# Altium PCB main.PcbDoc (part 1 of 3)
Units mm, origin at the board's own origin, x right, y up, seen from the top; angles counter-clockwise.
Board outline 326.29 x 232.51 mm, 2 copper layers (TopLayer, BottomLayer); 87 components, 134 nets, 466 pads, 108 vias.
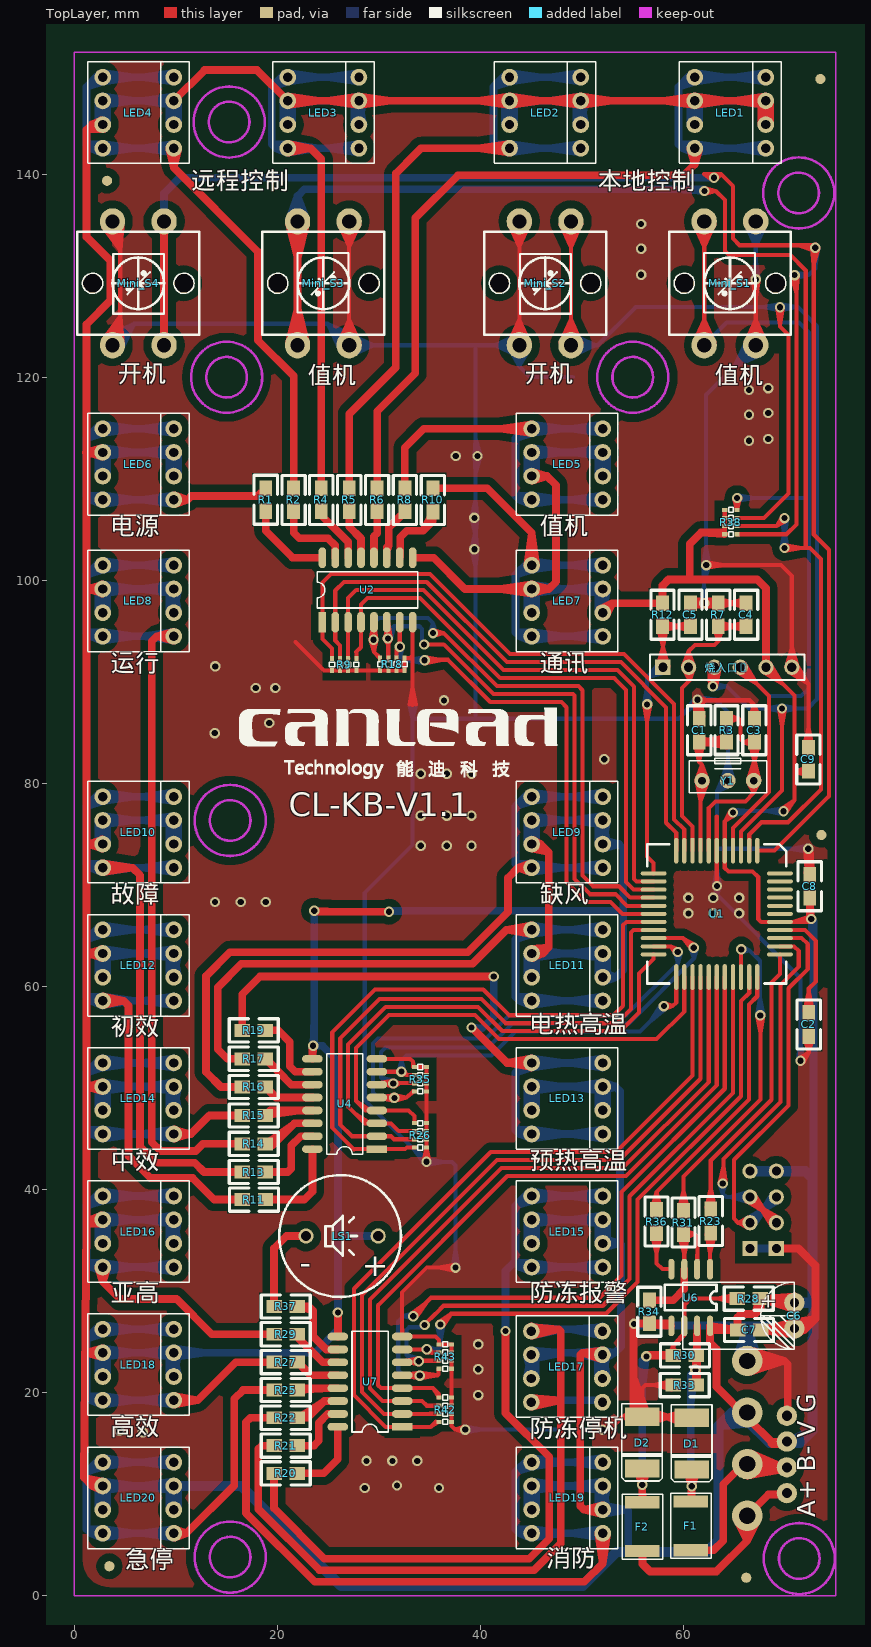
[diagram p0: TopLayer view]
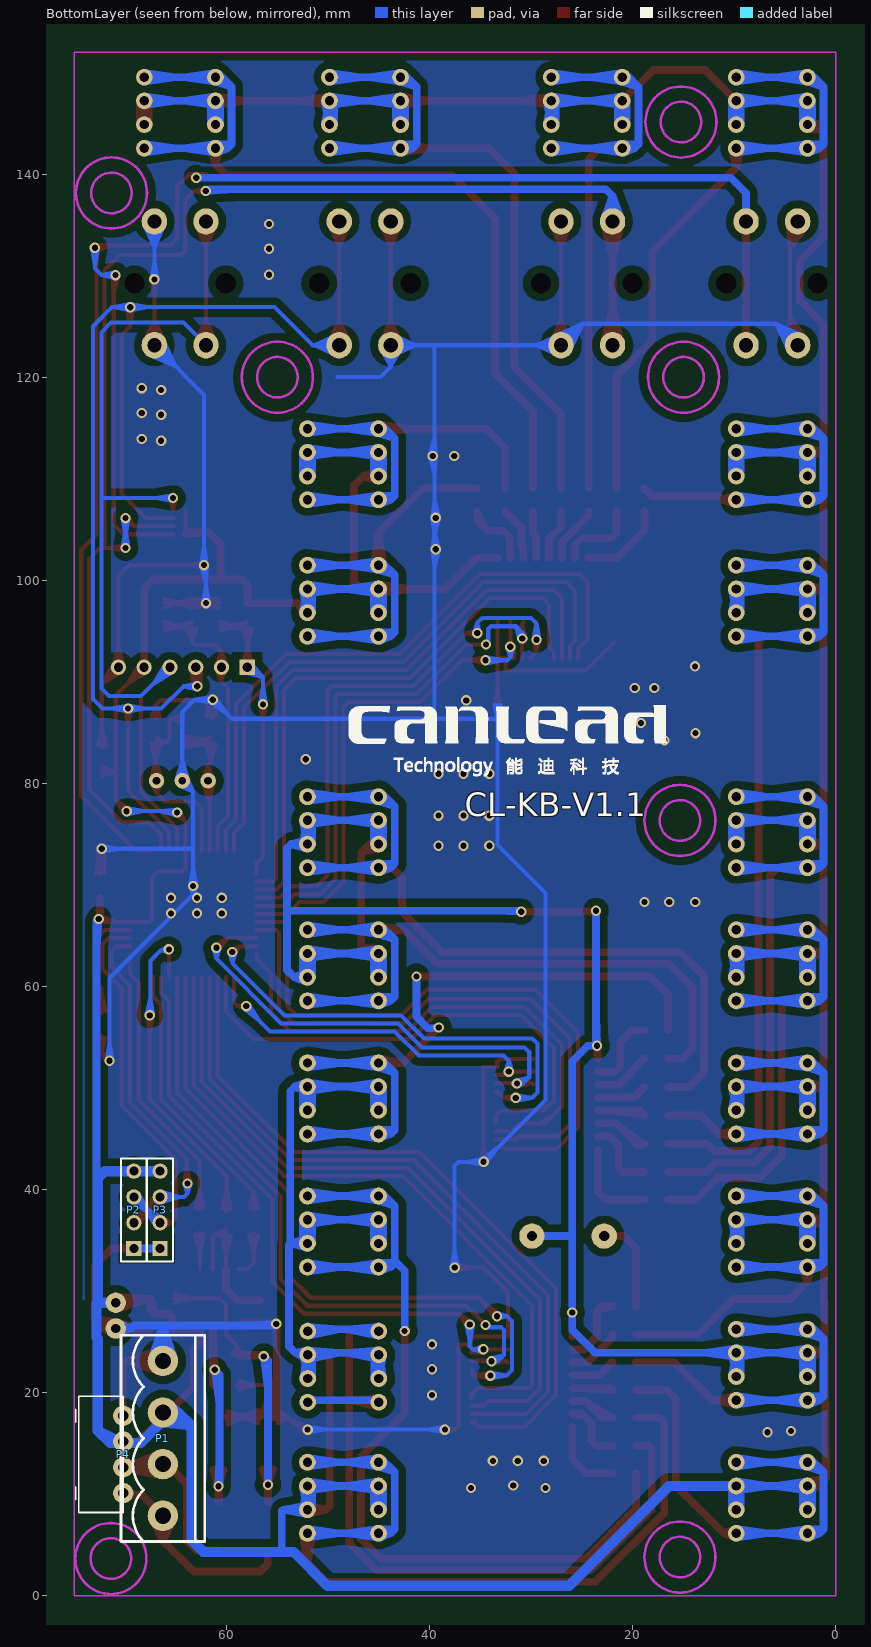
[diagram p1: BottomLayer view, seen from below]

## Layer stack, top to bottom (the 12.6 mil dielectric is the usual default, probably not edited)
TopLayer: signal copper 0.0356
Dielectric: dielectric 0.32, FR-4, Dk 4.8
BottomLayer: signal copper 0.0356

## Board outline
264.52,193.895 -60.795,193.895 -60.795,-38.612 265.497,-38.612 265.497,183.149

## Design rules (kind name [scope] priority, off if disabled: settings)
Clearance Clearance_1 [All] p1 off: gap=0.762
Clearance [All] p2: gap=0.381
ComponentClearance [All] p1 off: gap=0.254 collisioncheckmode=3 verticalgap=0.254 showdistances=FALSE
FabricationTestPointUsage TestPointUsage [All] p1: valid=0 allowmultiple=FALSE
FabricationTestpoint Testpoint [(IsPad And (OnTopLayer Or OnBottomLayer))] p1: side=3 testpointundercomponent=TRUE minsize=1.016 maxsize=2.54 preferedsize=1.524 minholesize=0.508 maxholesize=1.016 preferedholesize=0.813 testpointgrid=0.025 allowsidetop=TRUE allowsidebottom=TRUE usegrid=TRUE gridtolerance=0
PolygonConnect PolygonConnect_1 [All vs (InPadClass('All Pads'))] p1: connectstyle=NoConnect reliefconductorwidth=0.254 reliefentries=4 polygonreliefangle="90 Angle"
PolygonConnect [All] p2: connectstyle=Direct reliefconductorwidth=0.254 reliefentries=4 polygonreliefangle="90 Angle"
RoutingVias [All] p1: holewidth=0.61 width=1.016 viastyle="Through Hole" minholewidth=0.61 minwidth=1.016 maxholewidth=0.61 maxwidth=1.016
SilkscreenOverComponentPads [All] p1: minsilkscreentomaskgap=0.254
SolderMaskExpansion [All] p1: expansion=0.102
Width [All] p1: maxlimit=7.62 minlimit=0.254 preferedwidth=0.762
24 further rules are at their usual default settings.

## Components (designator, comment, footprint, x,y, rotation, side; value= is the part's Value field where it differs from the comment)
C1 "22p" 0805 61.551,84.093 r90 top
C2 "104" 0805 72.339,55.118 r90 top
C3 "22p" 0805 66.987,84.093 r90 top
C4 "104" 0805 66.174,95.472 r90 top
C5 "104" 0805 60.687,95.472 r90 top
C6 "470u/16V" E6.5MM*10 70.917,27.584 r270 top
C7 "104" 0805 65.329,26.162 r0 top
C8 "104" 0805 72.441,68.732 r90 top
C9 "104" 0805 72.3,81.225 r90 top
D1 "SMBJ6.8" SMBJ_SMT 60.808,14.986 r270 top
D2 "SMBJ6.8" SMBJ_SMT 55.93,15.081 r270 top
F1 "X14" PPTC_SMT 60.73,6.881 r90 top
F2 "X14" PPTC_SMT 55.955,6.806 r90 top
LED1 "GREEN" PLED10*10 64.599,146.05 r0 top
LED2 "GREEN" PLED10*10 46.369,146.05 r0 top
LED3 "GREEN" PLED10*10 24.529,146.05 r0 top
LED4 "GREEN" PLED10*10 6.299,146.05 r0 top
LED5 "GREEN" PLED10*10 48.539,111.43 r0 top
LED6 "GREEN" PLED10*10 6.299,111.43 r0 top
LED7 "GREEN" PLED10*10 48.539,97.98 r0 top
LED8 "GREEN" PLED10*10 6.299,97.98 r0 top
LED9 "RED" PLED10*10 48.539,75.19 r0 top
LED10 "RED" PLED10*10 6.299,75.19 r0 top
LED11 "RED" PLED10*10 48.539,62.08 r0 top
LED12 "RED" PLED10*10 6.299,62.08 r0 top
LED13 "RED" PLED10*10 48.539,48.97 r0 top
LED14 "RED" PLED10*10 6.299,48.97 r0 top
LED15 "RED" PLED10*10 48.539,35.86 r0 top
LED16 "RED" PLED10*10 6.299,35.86 r0 top
LED17 "RED" PLED10*10 48.514,22.555 r0 top
LED18 "RED" PLED10*10 6.299,22.75 r0 top
LED19 "RED" PLED10*10 48.539,9.64 r0 top
LED20 "RED" PLED10*10 6.299,9.64 r0 top
LS1 "Speaker" SPK 29.921,35.408 r180 top
Mini_S1 "" KEYL 64.574,129.25 r270 top
Mini_S2 "" KEYL 46.369,129.25 r90 top
Mini_S3 "" KEYL 24.529,129.25 r270 top
Mini_S4 "" KEYL 6.299,129.25 r90 top
P1 "Header 4" PL4X 66.275,15.5 r270 bottom
P2 "Header 4" HDR1X4 69.139,34.188 r90 bottom
P3 "Header 4" HDR1X4 66.548,34.188 r90 bottom
P4 "Header 4" C3-4L 70.175,13.91 r270 bottom
R1 "220" 0805 18.849,109.072 r270 top
R2 "220" 0805 21.592,109.067 r270 top
R3 "1M" 0805 64.243,84.093 r90 top
R4 "220" 0805 24.317,109.067 r270 top
R5 "220" 0805 27.067,109.067 r270 top
R6 "220" 0805 29.817,109.067 r270 top
R7 "3K" 0805 63.431,95.472 r90 top
R8 "220" 0805 32.542,109.067 r270 top
R9 "Res Pack42" RES4 25.374,91.1 r0 top
R10 "220" 0805 35.299,109.05 r270 top
R11 "220" 0805 16.549,39 r0 top
R12 "3K" 0805 57.944,95.472 r90 top
R13 "220" 0805 16.533,41.717 r0 top
R14 "220" 0805 16.533,44.492 r0 top
R15 "220" 0805 16.533,47.292 r0 top
R16 "220" 0805 16.533,50.092 r0 top
R17 "220" 0805 16.533,52.867 r0 top
R18 "Res Pack4" RES4 30.124,91.125 r0 top
R19 "220" 0805 16.533,55.667 r0 top
R20 "220" 0805 19.683,12.042 r0 top
R21 "220" 0805 19.683,14.767 r0 top
R22 "220" 0805 19.683,17.517 r0 top
R23 "100" 0805 62.687,35.763 r90 top
R25 "220" 0805 19.683,20.242 r0 top
R26 "Res Pack4" RES4 34.692,44.142 r90 top
R27 "220" 0805 19.683,22.992 r0 top
R28 "3K" 0805 67.564,29.261 r180 top
R29 "220" 0805 19.683,25.742 r0 top
R30 "10K?" 0805 61.265,23.673 r180 top
R31 "100" 0805 59.995,35.611 r90 top
R33 "3K" 0805 58.979,20.726 r0 top
R34 "30K" 0805 56.642,26.822 r90 top
R35 "Res Pack4" RES4 34.692,49.667 r90 top
R36 "100" 0805 57.353,35.712 r90 top
R37 "220" 0805 21.958,28.492 r180 top
R38 "Res Pack42" RES4 64.059,106.934 r270 top
R42 "Res Pack4" RES4 37.135,17.12 r90 top
R43 "Res Pack4" RES4 37.135,22.352 r90 top
U1 "QFP44" QFP44 63.274,67.15 r270 top
U2 "2003" SO_16 28.874,99.05 r0 top
U4 "2003" SO_16 26.624,48.425 r90 top
U6 "U485" SOP8 60.706,29.362 r180 top
U7 "2003" SO_16 29.124,21.075 r90 top
Y1 "10M" X3 64.364,80.264 r0 top
烧入口1 "Rin1" HDR1X6 57.963,91.44 r0 top

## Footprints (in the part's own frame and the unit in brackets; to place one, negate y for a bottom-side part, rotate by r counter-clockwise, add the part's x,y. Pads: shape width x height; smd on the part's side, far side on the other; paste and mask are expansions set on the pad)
0805 [mil]
  rect 60x50 smd: 1(-0.2,0.31) 2(89.8,0.31)
  silkscreen extent -50,-45 140,45
C3-4L [mm]
  round 2 hole 1: 1(-3.81,0) 2(-1.27,0) 3(1.27,0) 4(3.81,0)
  silkscreen extent -5.72,-4.7 5.71,0
E6.5MM*10 [mm]
  round 2 hole 0.9: 1(-1.27,0) 2(1.27,0)
  silkscreen extent -3.3,-11 3.3,0
HDR1X4 [mm] "Connector; Header; 4 Position"
  rect 1.5x1.5 hole 0.9: 1(0,0)
  round 1.5 hole 0.9: 2(2.54,0) 3(5.08,0) 4(7.62,0)
  silkscreen extent -1.27,-1.27 8.89,1.27
HDR1X6 [mm] "Connector;"
  rect 1.5x1.5 hole 0.9: 1(0,0)
  round 1.5 hole 0.9: 2(2.54,0) 3(5.08,0) 4(7.62,0) 5(10.16,0) 6(12.7,0)
  silkscreen extent -1.27,-1.27 13.97,1.27
KEYL [mil]
  round 65 hole 78.74 unplated: 0(0,177.17) 0(0,-177.17)
  oval 102x98 hole 55: 1(-240,-100) 1(240,-100) 2(-240,100) 2(240,100)
  silkscreen extent -200,-236 200,236
PL4X [mm]
  round 3 hole 1.6: 1(-7.62,0) 2(-2.54,0) 3(2.54,0) 4(7.62,0)
  silkscreen extent -10.16,-4.13 10.16,4.13
PLED10*10 [mil]
  round 65 hole 36: A(-137.8,-45.93) A(-137.8,45.93) A(137.8,-45.93) A(137.8,45.93) K(-137.8,-137.8) K(-137.8,137.8) K(137.8,-137.8) K(137.8,137.8)
  silkscreen extent -197,-197 197,197
PPTC_SMT [mm]
  rect 1.2x3.4 smd: 1(-2.4,0) 2(2.4,0)
  silkscreen extent -3.2,-2 3.2,2
QFP44 [mil]
  oval 100x16 smd: 1(-245,157) 2(-245,126) 3(-245,94) 4(-245,63) 5(-245,31) 6(-245,0) 7(-245,-31) 8(-245,-63) 9(-245,-94) 10(-245,-126) 11(-245,-157) 23(245,-157) 24(245,-126) 25(245,-94) 26(245,-63) 27(245,-31) 28(245,0) 29(245,31) 30(245,63) 31(245,94) 32(245,126) 33(245,157)
  oval 16x100 smd: 12(-157,-245) 13(-126,-245) 14(-94,-245) 15(-63,-245) 16(-31,-245) 17(0,-245) 18(31,-245) 19(63,-245) 20(94,-245) 21(126,-245) 22(157,-245) 34(157,245) 35(126,245) 36(94,245) 37(63,245) 38(31,245) 39(0,245) 40(-31,245) 41(-63,245) 42(-94,245) 43(-126,245) 44(-157,245)
  silkscreen extent -270,-270 270,270
RES4 [mm]
  rect 0.4x0.5 smd: 1(0,0) 2(0.8,0) 3(1.6,0) 4(2.4,0) 5(2.4,1.2) 6(1.6,1.2) 7(0.8,1.2) 8(0,1.2)
  silkscreen extent -0.25,0.38 2.65,0.85
SMBJ_SMT [mm]
  rect 1.778x3.4 smd: A(-2.54,0) K(2.54,0)
  silkscreen extent -3.81,-2 3.78,2
SO_16 [mil]
  rect 30x80 smd: 1(-175,-125)
  oval 30x80 smd: 2(-125,-125) 3(-75,-125) 4(-25,-125) 5(25,-125) 6(75,-125) 7(125,-125) 8(175,-125) 9(175,125) 10(125,125) 11(75,125) 12(25,125) 13(-25,125) 14(-75,125) 15(-125,125) 16(-175,125)
  silkscreen extent -195,-70 195,70
SOP8 [mil]
  oval 24x80 smd: 1(-75,-110) 2(-25,-110) 3(25,-110) 4(75,-110) 5(75,110) 6(25,110) 7(-25,110) 8(-75,110)
  silkscreen extent -100,-50 100,50
SPK [mm]
  round 1.5 / inner round 1.5 / far side round 2.5 hole 1: 1(-0.007,-0.008) 2(7.105,-0.008)
  silkscreen extent -2.26,-6.01 9.74,5.99
X3 [mil]
  round 60 hole 30: 1(-100,0) 2(100,0) 3(0,0)
  silkscreen extent -150,-47 150,107

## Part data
C1 C2 C3 C4 C5 C6 C7 C8 C9: library part CAP, "Capacitor"
D1 D2: library part DIODE, "Diode"
F1 F2: library part "Fuse 1", "Fuse"
LED1 LED2 LED3 LED4 LED5 LED6 LED7 LED8 LED9 LED10 LED11 LED12 LED13 LED14 LED15 LED16 LED17 LED18 LED19 LED20: library part LED, "Zener Diode"
LS1: "Loudspeaker"
Mini_S1 Mini_S2 Mini_S3 Mini_S4: library part SW-PB, "Switch"
P1 P2 P3 P4: "Header, 4-Pin"
R1 R2 R3 R4 R5 R6 R7 R8 R10 R11 R12 R13 R14 R15 R16 R17 R19 R20 R21 R22 R23 R25 R27 R28 R29 R30 R31 R33 R34 R36 R37: library part RES2
R9 R38: library part "Res Pack4", "Isolated Resistor Network"
R18 R26 R35 R42 R43: "Isolated Resistor Network"
U1: library part S3F84UA
U2 U4 U7: library part ULN2003A, "High-Voltage, High-Current Darlington Array"
Y1: library part CRYSTAL2
烧入口1: library part "Header 6", "Header, 6-Pin"

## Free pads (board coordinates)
  round 1 smd: 1(3.224,139.346) 1(3.45,2.9) 1(66.174,1.771) 1(73.474,149.371) 1(73.574,74.921)
  round 2.2 on Top Solder: 2(3.224,139.346) 2(3.45,2.9) 2(31.274,5.571) 2(66.174,1.771) 2(73.474,149.371) 2(73.574,74.921)

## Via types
v1: diameter 1.016, hole 0.61, TopLayer to BottomLayer, tented both sides, 108 vias

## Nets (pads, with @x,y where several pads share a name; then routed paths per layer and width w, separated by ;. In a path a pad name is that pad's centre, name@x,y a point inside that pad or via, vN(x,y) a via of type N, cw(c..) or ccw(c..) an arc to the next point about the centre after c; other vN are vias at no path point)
AD1: U1.42
AD2: U1.41
AD3: U1.40
AD4: U1.39
DE/RE: U1.43
DE/RE2: R31.2 U1.31 | length 52.8
  TopLayer w0.406: R31.2@59.558,38.069 59.987,39.873 ; R31.2@59.987,37.892 59.987,41.288 67.564,48.865 v1(67.564,57.15) 67.564,55.423 ; R31.2@59.987,38.019 59.987,39.873 ; R31.2@60.416,38.069 59.987,39.873 ; U1.31@65.662,60.927 65.662,63.63 v1(65.684,63.652) ; U1.31@65.662,61.994 v1@65.662,63.416 ; v1@67.26,57.123 67.564,55.423 ; v1@67.868,57.123 67.564,55.423
  BottomLayer w0.406: v1@65.704,63.348 66.497,63.551 ; v1@65.778,63.943 66.497,63.551 ; v1@67.26,57.168 67.513,58.88 ; v1@67.867,57.186 67.513,58.88 ; 66.497,63.551 65.583,63.551 v1(65.684,63.652) 66.497,63.551 ; 66.497,63.551 67.513,62.535 67.513,57.201 v1(67.564,57.15) 67.513,58.88
DL_CLK: 
DL_SDA: 
GND: C1.2 C2.1 C3.2 C4.2 C5.2 C6.2 C7.2 C8.2 C9.2 D1.A D2.A Mini_S1.2 Mini_S2.2 Mini_S3.2 Mini_S4.2 P1.1 P2.1 P3.1 P4.1 R7.2 R9.1 R9.2 R9.3 R9.4 R18.1 R18.2 R18.3 R18.4 R18.5 R26.1 R26.2 R26.3 R26.4 R33.1 R34.1 R35.1 R35.2 R35.3 R35.4 R35.5 R42.1 R42.2 R42.3 R42.4 R43.1 R43.2 R43.3 R43.4 R43.5 U1.6 U2.8 U4.8 U6.5 U7.8 Y1.3 烧入口1.6 | length 1190.7
  TopLayer w0.406: Mini_S4.2@2.821,123.656 4.526,126.002 ; Mini_S4.2@2.821,134.844 4.526,132.498 ; Mini_S4.2@3.169,123.439 4.526,126.002 ; Mini_S4.2@3.169,135.061 4.526,132.498 ; Mini_S4.2@3.541,123.274 4.526,126.002 ; Mini_S4.2@3.541,135.226 4.526,132.498 ; Mini_S4.2@3.759,123.154 4.526,123.921 4.526,134.579 Mini_S4.2@3.759,135.346 ; Mini_S4.2@3.759,123.205 4.526,126.002 ; Mini_S4.2@3.759,135.295 4.526,132.498 ; Mini_S4.2@3.982,123.153 4.526,126.002 ; Mini_S4.2@3.982,135.347 4.526,132.498 ; Mini_S4.2@4.386,123.105 4.526,126.002 ; Mini_S4.2@4.386,135.395 4.526,132.498 ; Mini_S4.2@4.797,123.114 4.526,126.002 ; Mini_S4.2@4.797,135.386 4.526,132.498 ; 21.793,93.929 24.597,91.125 ; 24.754,91.125 R9.2@26.174,91.1 ; R9.1@25.543,91.103 R9.3@26.974,91.1 ; R9.1@25.554,91.125 R9.3@26.974,91.1 ; Mini_S3.2@26.051,123.425 27.069,125.669 ; Mini_S3.2@26.051,135.075 27.069,132.831 ; R9.2@26.343,91.103 R9.4@27.774,91.1 ; R9.2@26.354,91.125 R9.4@27.774,91.1 ; Mini_S3.2@26.439,123.287 27.069,125.669 ; Mini_S3.2@26.439,135.213 27.069,132.831 ; Mini_S3.2@26.841,123.215 27.069,125.669 ; Mini_S3.2@26.841,135.285 27.069,132.831 ; Mini_S3.2@27.069,123.154 Mini_S3.2@27.069,135.346 ; Mini_S3.2@27.069,123.205 27.069,125.669 ; Mini_S3.2@27.069,135.295 27.069,132.831 ; Mini_S3.2@27.298,123.215 27.069,125.669 ; Mini_S3.2@27.298,135.285 27.069,132.831 ; Mini_S3.2@27.699,123.287 27.069,125.669 ; Mini_S3.2@27.699,135.213 27.069,132.831 ; Mini_S3.2@28.087,123.425 27.069,125.669 ; Mini_S3.2@28.087,135.075 27.069,132.831 ; 28.705,91.125 R18.1@30.124,91.125 ; 29.195,91.125 R9.4@27.774,91.1 ; U4.8@29.799,52.87 33.079,52.87 33.349,52.6 ; U4.8@30.434,52.87 32.034,52.87 ; 32.282,27.121 U7.8@32.299,25.52 ; U7.8@32.934,25.52 34.534,25.52 ; 33.021,87.758 33.319,89.459 ; 33.319,93.64 U2.8@33.319,95.24 ; U2.8@33.319,95.875 33.319,92.595 ; R35.5@33.349,52.075 33.349,52.6 ; R35.5@33.442,52.067 33.349,52.6 ; 33.628,87.759 33.319,89.459 ; 34.692,48.247 R35.1@34.692,49.667 ; 37.135,20.933 R43.1@37.135,22.352 ; v1@37.514,32.005 35.814,32.309 ; v1@37.514,32.612 35.814,32.309 ; v1@38.461,16.056 37.49,16.358 ; v1@38.461,16.659 37.49,16.358 ; v1(38.506,16.358) 37.49,16.358 ; Mini_S2.2@42.811,123.425 43.829,125.669 ; Mini_S2.2@42.811,135.075 43.829,132.831 ; Mini_S2.2@43.2,123.287 43.829,125.669 ; Mini_S2.2@43.199,135.213 43.829,132.831 ; Mini_S2.2@43.601,123.215 43.829,125.669 ; Mini_S2.2@43.601,135.285 43.829,132.831 ; Mini_S2.2@43.829,123.154 Mini_S2.2@43.829,135.346 ; Mini_S2.2@43.829,123.205 43.829,125.669 ; Mini_S2.2@43.829,135.295 43.829,132.831 ; Mini_S2.2@44.058,123.215 43.829,125.669 ; Mini_S2.2@44.058,135.285 43.829,132.831 ; Mini_S2.2@44.459,123.287 43.829,125.669 ; Mini_S2.2@44.459,135.213 43.829,132.831 ; Mini_S2.2@44.847,123.425 43.829,125.669 ; Mini_S2.2@44.847,135.075 43.829,132.831 ; v1@51.886,16.632 53.73,17.357 ; v1@52.193,16.107 53.73,17.357 ; D2.A@54.91,16.968 53.994,17.621 ; D2.A@54.91,18.274 53.994,17.621 ; D2.A@55.084,17.344 53.994,17.621 ; D2.A@55.084,17.898 53.994,17.621 ; D2.A@55.119,17.621 53.994,17.621 ; D2.A@55.253,17.733 55.93,19.729 ; D2.A@55.651,17.64 55.93,19.729 ; D2.A@56.209,17.64 55.93,19.729 ; D2.A@56.607,17.733 55.93,19.729 ; D2.A@56.741,17.621 58.849,17.621 ; D2.A@56.76,17.342 58.849,17.621 ; D2.A@56.76,17.9 58.849,17.621 ; D2.A@56.853,16.945 58.849,17.621 ; D2.A@56.853,18.298 58.849,17.621 ; R33.1@58.796,20.305 56.992,20.734 ; R33.1@58.796,21.163 56.992,20.734 ; R33.1@58.847,20.734 56.992,20.734 ; R33.1@58.974,20.734 56.243,20.734 55.93,20.421 D2.A@55.93,17.621 ; D1.A@59.855,16.855 57.887,17.621 ; D1.A@59.916,18.207 57.887,17.621 ; D1.A@59.966,17.248 57.887,17.621 ; D1.A@59.991,17.805 57.887,17.621 ; D1.A@59.997,17.526 57.887,17.621 ; D1.A@60.808,17.526 60.712,17.621 D2.A@55.93,17.621 ; v1@61.062,88.257 C1.2@61.12,86.589 ; v1@61.09,88.111 C1.2@61.966,86.589 ; C1.2@61.543,86.374 61.543,87.567 ; v1@61.661,88.318 C1.2@61.966,86.589 ; v1@61.663,88.167 C1.2@61.12,86.589 ; v1@61.898,97.477 C5.2@60.749,98.179 ; v1@61.898,98.03 C5.2@60.749,97.327 ; v1@61.966,97.455 R7.2@63.356,97.327 ; v1@61.966,98.052 R7.2@63.356,98.18 ; v1@61.992,97.45 C5.2@60.68,97.753 ; v1@61.992,98.056 C5.2@60.68,97.753 ; v1@62.06,97.45 R7.2@63.423,97.753 ; v1@62.06,98.056 R7.2@63.423,97.753 ; v1@62.09,97.455 C5.2@60.749,97.327 ; v1@62.09,98.051 C5.2@60.749,98.179 ; v1@62.151,97.475 R7.2@63.356,98.18 ; v1@62.151,98.032 R7.2@63.356,97.327 ; v1(62.23,101.498) 69.596,101.498 70.663,100.432 烧入口1.6@70.663,91.44 72.292,89.811 C9.2@72.292,83.506 ; v1@62.257,101.195 63.957,101.498 v1@62.257,101.802 ; 63.274,70.884 U1.6@63.274,72.306 ; U1.6@63.274,74.44 63.274,75.862 ; 63.274,76.736 U1.6@63.274,73.373 63.274,69.923 v1(63.297,69.901) ; R7.2@63.473,97.324 65.277,97.753 R7.2@63.473,98.182 ; Mini_S1.2@66.096,123.425 67.114,125.669 ; C4.2@66.116,97.324 64.312,97.753 C4.2@66.116,98.182 ; C4.2@66.166,97.753 R7.2@63.423,97.753 ; Mini_S1.2@66.484,123.287 67.114,125.669 ; C3.2@66.554,86.578 66.979,87.707 ; v1@66.81,129.612 67.114,127.912 ; Mini_S1.2@66.885,123.215 67.114,125.669 ; C3.2@66.979,86.374 66.979,87.707 ; C3.2@66.979,86.501 66.979,87.707 ; Mini_S1.2@67.114,123.154 v1@67.114,129.861 ; Mini_S1.2@67.114,123.205 67.114,125.669 ; v1@67.114,129.6 v1(67.114,129.639) 67.114,127.912 ; Mini_S1.2@67.342,123.215 67.114,125.669 ; C3.2@67.404,86.578 66.979,87.707 ; v1@67.417,129.612 67.114,127.912 ; Mini_S1.2@67.744,123.287 67.114,125.669 ; Mini_S1.2@68.132,123.425 67.114,125.669 ; 烧入口1.6@70.121,91.516 70.663,93.409 烧入口1.6@71.204,91.516 ; 烧入口1.6@70.325,91.01 72.275,89.828 烧入口1.6@71.093,91.777 ; v1@71.342,52.922 72.331,53.485 ; v1(71.526,52.68) 72.331,53.485 ; v1@71.769,52.495 72.331,53.485 ; C9.2@71.863,83.683 72.292,85.487 ; C2.1@71.904,54.924 72.331,53.485 ; v1@71.984,73.565 C8.2@72.096,71.577 ; v1@72,73.461 72.701,71.866 ; C8.2@72.004,71.19 72.433,72.994 ; C9.2@72.292,83.633 72.292,85.487 ; C2.1@72.331,54.986 72.331,53.485 ; C2.1@72.331,55.113 72.331,53.485 ; C8.2@72.433,71.013 72.433,73.414 v1(72.288,73.558) ; C8.2@72.433,71.14 72.433,72.994 ; v1@72.589,73.506 C8.2@72.096,71.577 ; v1@72.59,73.604 72.701,71.866 ; C9.2@72.721,83.683 72.292,85.487 ; C2.1@72.759,54.924 72.331,53.485 ; C8.2@72.862,71.19 72.433,72.994 ; 24.597,91.125 R18.1@30.124,91.125 ; 24.597,91.125 R9.1@25.374,91.1 ; R9.1@25.374,91.1 26.795,91.125 R9.2@26.174,91.1 ; R9.1@25.374,91.1 R9.2@26.174,91.1 ; R9.2@26.174,91.1 27.595,91.125 R9.3@26.974,91.1 ; R9.2@26.174,91.1 R9.3@26.974,91.1 ; R9.2@26.174,91.1 R9.3@26.974,91.1 ; R9.3@26.974,91.1 28.395,91.125 R9.4@27.774,91.1 ; R9.3@26.974,91.1 R9.4@27.774,91.1 ; R9.3@26.974,91.1 R9.4@27.774,91.1 ; R18.1@30.124,91.125 R18.2@30.924,91.125 ; R18.1@30.124,91.125 R18.2@30.924,91.125 ; R18.2@30.924,91.125 R18.3@31.724,91.125 ; R18.2@30.924,91.125 R18.3@31.724,91.125 ; R18.3@31.724,91.125 R18.4@32.524,91.125 ; R18.3@31.724,91.125 R18.4@32.524,91.125 ; U7.8@32.299,25.52 35.579,25.52 35.935,25.164 R43.5@35.935,24.752 ; U7.8@32.299,25.52 32.282,25.537 32.282,29.857 34.734,32.309 v1(37.541,32.309) 35.814,32.309 ; R18.4@32.524,91.125 R18.5@32.524,92.325 ; R18.4@32.524,91.125 32.524,92.275 32.524,91.175 R18.5@32.524,92.325 ; R18.5@32.524,92.325 33.049,92.325 33.319,92.595 ; 33.319,89.459 33.325,87.732 33.319,87.737 33.319,92.595 ; R26.1@34.692,44.142 v1(34.692,42.728) R26.1@34.692,44.142 ; R26.1@34.692,44.142 R26.2@34.692,44.942 ; R26.1@34.692,44.142 R26.2@34.692,44.942 ; R26.1@34.692,44.142 34.389,42.76 R26.1@34.692,44.142 ; R26.1@34.692,44.142 34.995,42.76 R26.1@34.692,44.142 ; R26.2@34.692,44.942 R26.3@34.692,45.742 ; R26.2@34.692,44.942 R26.3@34.692,45.742 ; R26.3@34.692,45.742 R26.4@34.692,46.542 ; R26.3@34.692,45.742 R26.4@34.692,46.542 ; R26.4@34.692,46.542 R35.1@34.692,49.667 ; R35.1@34.692,49.667 R35.2@34.692,50.467 ; R35.1@34.692,49.667 R35.2@34.692,50.467 ; R35.2@34.692,50.467 R35.3@34.692,51.267 ; R35.2@34.692,50.467 R35.3@34.692,51.267 ; R35.3@34.692,51.267 R35.4@34.692,52.067 ; R35.3@34.692,51.267 R35.4@34.692,52.067 ; R35.4@34.692,52.067 R35.5@33.492,52.067 34.642,52.067 33.542,52.067 R35.4@34.692,52.067 ; R43.5@35.935,24.752 R43.4@37.135,24.752 ; R43.5@35.935,24.752 37.085,24.752 35.985,24.752 R43.4@37.135,24.752 ; 37.135,16.713 37.49,16.358 ; 37.135,16.713 R42.1@37.135,17.12 ; 37.135,16.713 R42.1@37.135,17.12 ; R42.1@37.135,17.12 R42.2@37.135,17.92 ; R42.1@37.135,17.12 R42.2@37.135,17.92 ; R42.2@37.135,17.92 R42.3@37.135,18.72 ; R42.2@37.135,17.92 R42.3@37.135,18.72 ; R42.3@37.135,18.72 R42.4@37.135,19.52 ; R42.3@37.135,18.72 R42.4@37.135,19.52 ; R42.4@37.135,19.52 R43.1@37.135,22.352 ; R43.1@37.135,22.352 R43.2@37.135,23.152 ; R43.1@37.135,22.352 R43.2@37.135,23.152 ; R43.2@37.135,23.152 R43.3@37.135,23.952 ; R43.2@37.135,23.152 R43.3@37.135,23.952 ; R43.3@37.135,23.952 R43.4@37.135,24.752 ; R43.3@37.135,23.952 R43.4@37.135,24.752 ; v1(52.019,16.358) 52.73,16.358 ; v1(52.019,16.358) 53.73,17.357 ; v1(52.019,16.358) 52.73,16.358 ; 52.73,16.358 53.994,17.621 ; 52.73,16.358 52.085,16.655 52.73,16.358 ; 52.73,16.358 52.085,16.06 52.73,16.358 ; 53.994,17.621 D2.A@55.93,17.621 ; C5.2@60.68,97.753 v1(62.027,97.753) ; C5.2@60.749,97.327 v1(62.027,97.753) ; C5.2@60.749,98.179 v1(62.027,97.753) ; v1@61.096,88.099 61.543,87.567 ; v1@61.096,88.099 61.543,87.567 ; v1@61.096,88.099 61.543,87.567 ; v1@61.096,88.099 61.543,87.567 ; v1@61.096,88.099 61.543,87.567 ; C1.2@61.12,86.589 61.543,87.567 ; C1.2@61.12,86.589 v1(61.366,88.24) ; v1(61.366,88.24) 61.417,88.189 62.165,88.189 ; v1(61.366,88.24) 61.543,87.567 ; v1(61.366,88.24) C1.2@61.543,86.496 ; v1(61.366,88.24) 61.543,87.567 ; v1(61.366,88.24) C1.2@61.966,86.589 ; v1(61.366,88.24) 61.543,87.567 ; v1(61.366,88.24) 61.543,87.567 ; v1(61.366,88.24) C1.2@61.543,86.501 ; v1(61.366,88.24) 62.165,88.189 ; v1(61.366,88.24) 62.165,88.189 ; v1(61.366,88.24) 61.543,87.567 ; C1.2@61.543,86.496 61.671,88.244 C1.2@61.543,86.501 ; C1.2@61.543,86.496 61.067,88.183 C1.2@61.543,86.501 ; C1.2@61.543,86.501 61.543,87.567 ; 61.543,87.567 62.165,88.189 ; 61.543,87.567 C1.2@61.966,86.589 ; 61.543,87.567 v1@61.671,88.251 ; 61.543,87.567 v1@61.671,88.251 ; 61.543,87.567 v1@61.671,88.251 ; 61.543,87.567 v1@61.671,88.251 ; 61.543,87.567 v1@61.671,88.251 ; v1(62.027,97.753) R7.2@63.423,97.753 ; v1(62.027,97.753) R7.2@63.356,97.327 ; v1(62.027,97.753) R7.2@63.356,98.18 ; 62.165,88.189 66.497,88.189 66.979,87.707 ; 62.165,88.189 61.443,88.535 62.165,88.189 ; 62.165,88.189 61.405,87.937 62.165,88.189 ; v1@72.023,73.408 72.433,72.994 ; v1@72.023,73.408 72.433,72.994 ; v1@72.023,73.408 72.433,72.994 ; C8.2@72.096,71.577 v1(72.288,73.558) ; v1(72.288,73.558) 72.433,71.813 ; v1(72.288,73.558) 72.433,72.994 ; v1(72.288,73.558) 72.701,71.866 ; v1(72.288,73.558) 72.433,72.994 ; v1(72.288,73.558) 72.433,72.994 ; v1(72.288,73.558) 72.433,71.819 ; 72.433,71.813 72.593,73.557 72.433,71.819 ; 72.433,71.813 71.988,73.507 72.433,71.819 ; 72.433,72.994 v1@72.593,73.554 ; 72.433,72.994 v1@72.593,73.554 ; 72.433,72.994 v1@72.593,73.554
  TopLayer w0.762: 55.067,23.975 v1(55.118,26.772) ; D2.A@55.428,17.544 55.067,21.549 ; D2.A@56.418,17.761 55.067,21.549 ; R34.1@56.634,26.69 U6.5@58.801,26.568 R34.1@56.634,26.817 ; U6.5@58.552,26.817 R34.1@56.634,26.817 ; P1.1@66.275,23.12 69.93,23.12 ; P1.1@66.446,22.014 69.93,23.12 ; P1.1@66.446,24.226 69.93,23.12 ; C7.2@67.61,26.17 C6.2@70.772,26.17 ; P2.1@69.139,34.188 71.323,34.188 73,32.512 73,27.28 ; P4.1@70.256,17.577 70.256,22.794 69.93,23.12 ; C6.2@70.658,26.17 C7.2@67.737,26.17 ; C6.2@70.735,26.906 73,27.28 ; C6.2@70.829,26.927 C7.2@67.737,26.17 ; C6.2@70.832,26.928 C7.2@67.625,26.17 ; C6.2@70.885,25.696 C7.2@67.737,26.17 ; C6.2@70.886,25.696 C7.2@67.625,26.17 ; C6.2@71.25,25.793 73,27.28 ; 55.067,21.549 D2.A@55.93,17.621 55.067,18.484 55.067,26.721 v1(55.118,26.772) ; v1@55.113,26.817 R34.1@56.634,26.817 ; v1@55.113,26.817 55.113,26.777 v1(55.118,26.772) ; v1@55.113,26.817 R34.1@56.634,26.817 ; v1(55.118,26.772) R34.1@56.634,26.817 ; v1(55.118,26.772) R34.1@56.634,26.817 ; C7.2@67.625,26.17 C6.2@70.917,26.314 ; C7.2@67.737,26.17 C6.2@70.917,26.314 ; C6.2@70.772,26.17 71.89,26.17 73,27.28 ; C6.2@70.772,26.17 C6.2@70.917,26.314 ; C6.2@70.917,26.314 73,27.28
  BottomLayer w0.406: Mini_S4.2@3.175,124.067 5.866,125.261 ; Mini_S4.2@3.367,123.704 5.866,125.261 ; Mini_S4.2@3.606,123.374 5.866,125.261 ; Mini_S4.2@3.759,123.154 5.878,125.273 24.95,125.273 Mini_S3.2@27.069,123.154 39.522,123.154 ; Mini_S4.2@3.759,123.205 5.866,125.261 ; Mini_S4.2@3.925,123.048 5.866,125.261 ; Mini_S4.2@4.249,122.801 5.866,125.261 ; Mini_S4.2@4.607,122.6 5.866,125.261 ; Mini_S3.2@26.221,122.6 24.962,125.261 ; Mini_S3.2@26.579,122.801 24.962,125.261 ; Mini_S3.2@26.903,123.048 24.962,125.261 ; Mini_S3.2@27.069,123.205 24.962,125.261 ; Mini_S3.2@27.08,122.926 29.533,123.154 ; Mini_S3.2@27.08,123.382 29.533,123.154 ; Mini_S3.2@27.151,122.524 29.533,123.154 ; Mini_S3.2@27.151,123.784 29.533,123.154 ; Mini_S3.2@27.222,123.374 24.962,125.261 ; Mini_S3.2@27.289,122.136 29.533,123.154 ; Mini_S3.2@27.289,124.172 29.533,123.154 ; Mini_S3.2@27.461,123.704 24.962,125.261 ; Mini_S3.2@27.653,124.067 24.962,125.261 ; 33.022,87.698 33.325,86.36 ; 33.325,87.732 33.325,86.36 ; 33.628,87.698 33.325,86.36 ; v1@34.46,42.53 33.321,44.098 v1@34.889,42.959 ; v1@34.718,42.424 36.419,42.728 v1@34.718,43.031 ; v1@37.238,32.336 37.541,34.036 v1@37.845,32.336 ; v1(37.541,32.309) 37.541,42.367 37.181,42.728 v1(34.692,42.728) 28.6,48.819 28.6,69.19 33.325,73.914 33.325,86.36 ; v1(38.506,16.358) v1(52.019,16.358) ; v1@38.533,16.054 40.234,16.358 v1@38.533,16.661 ; v1@39.099,103.002 39.522,101.309 ; v1@39.099,103.098 39.522,104.791 ; v1@39.099,106.102 39.522,104.409 ; v1@39.099,106.198 39.522,107.891 ; v1@39.395,112.246 39.522,114.005 ; v1@39.395,112.254 39.522,110.494 ; 39.522,86.563 39.522,123.154 ; v1@39.705,103.045 39.522,101.309 ; v1@39.705,103.055 39.522,104.791 ; v1@39.705,106.145 39.522,104.409 ; v1@39.705,106.155 39.522,107.891 ; v1@39.999,112.193 39.522,110.494 ; v1@39.999,112.307 39.522,114.005 ; Mini_S2.2@42.822,122.837 43.829,121.068 ; Mini_S2.2@43.202,123.004 43.829,121.068 ; Mini_S2.2@43.601,123.09 43.829,121.068 ; Mini_S2.2@43.609,122.136 41.365,123.154 ; Mini_S2.2@43.609,124.172 41.365,123.154 ; Mini_S2.2@43.747,122.524 41.365,123.154 ; Mini_S2.2@43.747,123.784 41.365,123.154 ; Mini_S2.2@43.819,122.926 41.365,123.154 ; Mini_S2.2@43.819,123.382 41.365,123.154 ; Mini_S2.2@43.829,123.103 43.829,121.068 ; Mini_S2.2@44.057,123.09 43.829,121.068 ; Mini_S2.2@44.456,123.004 43.829,121.068 ; Mini_S2.2@44.836,122.837 43.829,121.068 ; 49.089,120.04 44.856,120.04 43.829,121.068 ; v1@51.992,16.054 50.292,16.358 v1@51.992,16.661 ; v1@61.135,88.438 59.996,86.869 ; v1@61.393,87.936 63.094,88.24 v1@61.393,88.543 ; v1@61.564,88.008 59.996,86.869 ; v1@61.723,97.78 62.027,99.48 v1@62.33,97.78 ; v1@61.925,101.507 62.027,99.724 ; v1@61.926,101.525 62.23,103.226 v1@62.534,101.525 ; v1(62.027,97.753) 62.027,101.295 v1(62.23,101.498) ; v1@62.529,101.438 62.027,99.724 ; v1@62.993,69.928 63.297,71.628 v1@63.6,69.928 ; v1@62.997,69.847 v1@63.297,69.037 ; v1@63.597,69.847 v1@63.297,69.037 ; Y1.3@63.81,80.343 64.364,82.245 Y1.3@64.917,80.343 ; Y1.3@63.902,80.579 63.297,79.197 ; Y1.3@64.679,79.803 63.297,79.197 ; Mini_S1.2@66.096,135.075 67.114,132.831 ; Mini_S1.2@66.266,123.708 65.007,121.047 ; Mini_S1.2@66.484,135.213 67.114,132.831 ; Mini_S1.2@66.624,123.507 65.007,121.047 ; v1@66.81,129.666 67.114,131.366 v1@67.417,129.666 ; Mini_S1.2@66.885,135.285 67.114,132.831 ; Mini_S1.2@66.948,123.26 65.007,121.047 ; Mini_S1.2@67.114,123.103 65.007,121.047 ; Mini_S1.2@67.114,123.154 62.23,118.27 v1(62.23,101.498) ; v1(67.114,129.639) Mini_S1.2@67.114,135.346 ; Mini_S1.2@67.114,135.295 67.114,132.831 ; Mini_S1.2@67.267,122.934 65.007,121.047 ; Mini_S1.2@67.342,135.285 67.114,132.831 ; Mini_S1.2@67.506,122.604 65.007,121.047 ; Mini_S1.2@67.698,122.241 65.007,121.047 ; Mini_S1.2@67.743,135.213 67.114,132.831 ; Mini_S1.2@68.132,135.075 67.114,132.831 ; v1@71.223,52.706 71.526,54.407 v1@71.83,52.706 ; v1(71.526,52.68) 71.526,60.808 v1@63.297,69.037 ; v1@72.262,73.255 70.561,73.558 v1@72.262,73.862 ; v1(72.288,73.558) 63.482,73.558 63.297,73.373 ; 33.325,86.36 59.487,86.36 v1(61.366,88.24) ; 39.522,101.309 v1(39.4,103.05) 39.522,104.791 ; 39.522,104.409 v1(39.4,106.15) 39.522,107.891 ; 39.522,110.494 v1(39.7,112.25) 39.522,114.005 ; 39.522,123.154 Mini_S2.2@43.829,123.154 43.829,121.068 ; 59.996,86.869 v1(61.366,88.24) ; v1(61.366,88.24) 63.144,88.24 64.364,87.02 Y1.3@64.364,80.264 ; 62.027,99.724 v1(62.23,101.498) ; v1@63.297,69.037 v1(63.297,69.901) 63.297,73.373 ; 63.297,73.373 63.297,79.197 ; 63.297,79.197 Y1.3@64.364,80.264 ; 63.297,79.197 Y1.3@64.364,80.264
  BottomLayer w0.762: 57.941,26.619 v1(55.118,26.772) 55.27,26.619 69.139,26.619 69.139,26.586 69.411,26.314 ; P1.1@65.171,23.3 66.275,26.594 ; P1.1@66.275,23.12 66.275,26.594 ; P3.1@66.548,34.188 P2.1@69.139,34.188 ; P1.1@67.379,23.3 66.275,26.594 ; C6.2@70.79,25.709 69.411,26.314 ; C6.2@70.79,26.92 69.411,26.314 ; C6.2@70.917,26.314 69.411,26.314
  other v1: 28.6,10.6 35.925,10.6 31.775,10.85 28.775,13.275 31.325,13.275 33.775,13.275 6.725,16.1 4.425,16.225 39.775,19.75 39.775,22.3 39.775,24.75 60.475,67.2 62.925,67.2 65.475,67.2 13.85,68.325 16.4,68.325 18.85,68.325 60.475,68.725 62.925,68.725 65.475,68.725 34.125,73.85 36.675,73.85 39.125,73.85 34.125,76.825 36.675,76.825 39.125,76.825 34.125,80.95 36.675,80.95 39.125,80.95 52.2,82.375 16.875,84.225 13.825,84.95 19.2,85.95 36.4,88.175 17.875,89.4 19.8,89.4 13.875,91.525 37.575,112.25 66.45,113.75 68.35,113.925 66.45,116.3 68.35,116.475 66.45,118.75 68.35,118.925 55.825,130.1 55.825,132.65 55.825,135.1
IN-A+: F2.1 P1.4 P4.4 | length 29.7
  TopLayer w0.762: F2.1@55.955,4.406 55.955,3.125 56.693,2.388 63.238,2.388 66.275,5.425 ; P1.4@65.185,7.625 66.275,5.425 ; P1.4@67.365,7.625 66.275,5.425 ; 66.275,5.425 P1.4@66.275,7.88 ; 66.275,5.425 P1.4@66.275,7.88 ; P1.4@66.275,7.88 68.352,9.957 ; 68.352,9.957 70.256,9.957 68.352,9.957
IN-B-: F1.1 P1.3 P4.3 | length 43.4
  TopLayer w0.762: F1.1@60.73,4.481 62.952,4.481 ; F1.1@61.83,4.481 62.952,4.481 ; P1.3@66.567,14.04 P4.3@70.132,12.497 ; P1.3@66.571,14.039 P4.3@70.079,12.497 ; P1.3@67.22,12.497 70.256,12.497 65.422,12.497 63.9,10.975 63.9,5.429 62.952,4.481 ; P4.3@70.079,12.497 66.303,11.841 P4.3@70.132,12.497 ; P4.3@70.079,12.497 P1.3@66.275,12.96 P4.3@70.132,12.497
KEY1: Mini_S1.1 R38.8 U1.4 烧入口1.4 | length 147.8
  TopLayer w0.406: Mini_S1.1@61.016,123.425 62.034,125.669 ; Mini_S1.1@61.016,135.075 62.034,132.831 ; Mini_S1.1@61.404,123.287 62.034,125.669 ; Mini_S1.1@61.404,135.213 62.034,132.831 ; Mini_S1.1@61.805,123.215 62.034,125.669 ; Mini_S1.1@61.805,135.285 62.034,132.831 ; Mini_S1.1@62.034,123.154 Mini_S1.1@62.034,135.346 ; Mini_S1.1@62.034,123.205 62.034,125.669 ; Mini_S1.1@62.034,135.295 62.034,132.831 ; Mini_S1.1@62.262,123.215 62.034,125.669 ; Mini_S1.1@62.262,135.285 62.034,132.831 ; Mini_S1.1@62.664,123.287 62.034,125.669 ; Mini_S1.1@62.664,135.213 62.034,132.831 ; Mini_S1.1@63.052,123.425 62.034,125.669 ; Mini_S1.1@63.052,135.075 62.034,132.831 ; U1.4@64.874,73.373 64.874,75.593 ; U1.4@64.874,74.44 64.874,75.593 ; v1@64.975,108.068 R38.8@65.259,106.934 ; 烧入口1.4@65.245,91.01 67.195,89.828 烧入口1.4@66.013,91.777 ; v1@65.58,108.058 R38.8@65.259,106.934 ; 烧入口1.4@65.583,91.44 68.428,88.595 68.428,79.146 64.874,75.593 ; R38.8@65.259,106.934 65.259,108.083 v1(65.278,108.102) R38.8@65.259,106.934
  BottomLayer w0.406: Mini_S1.1@62.034,123.154 64.254,125.374 71.376,125.374 72.339,124.411 72.339,89.357 71.577,88.595 68.428,88.595 烧入口1.4@65.583,91.44 ; 烧入口1.4@65.245,91.01 67.195,89.828 烧入口1.4@66.013,91.777 ; v1(65.278,108.102) 72.339,108.102 ; v1@65.305,107.799 67.005,108.102 v1@65.305,108.406
KEY2: Mini_S2.1 R38.7 U1.3 烧入口1.3 | length 235.7
  TopLayer w0.406: Mini_S2.1@47.891,123.425 48.909,125.669 ; Mini_S2.1@47.891,135.075 48.909,132.831 ; Mini_S2.1@48.279,123.287 48.909,125.669 ; Mini_S2.1@48.279,135.213 48.909,132.831 ; Mini_S2.1@48.681,123.215 48.909,125.669 ; Mini_S2.1@48.681,135.285 48.909,132.831 ; Mini_S2.1@48.909,123.154 Mini_S2.1@48.909,135.346 ; Mini_S2.1@48.909,123.205 48.909,125.669 ; Mini_S2.1@48.909,135.295 48.909,132.831 ; Mini_S2.1@49.138,123.215 48.909,125.669 ; Mini_S2.1@49.138,135.285 48.909,132.831 ; Mini_S2.1@49.539,123.287 48.909,125.669 ; Mini_S2.1@49.539,135.213 48.909,132.831 ; Mini_S2.1@49.927,123.425 48.909,125.669 ; Mini_S2.1@49.927,135.075 48.909,132.831 ; 烧入口1.3@62.503,91.353 v1@63.043,89.713 ; v1@62.588,89.523 烧入口1.3@62.524,91.291 ; v1@62.617,89.695 烧入口1.3@63.536,91.211 ; v1@63.182,89.649 烧入口1.3@62.524,91.291 ; v1@63.183,89.474 烧入口1.3@63.536,91.211 ; 烧入口1.3@63.583,91.353 v1@63.043,89.713 ; R38.7@65.259,106.134 67.932,106.134 70.333,108.534 70.333,124.17 69.494,125.008 v1(69.494,126.898) 69.494,125.171 ; R38.7@65.309,106.134 66.728,106.134 ; U1.3@65.662,73.373 65.662,75.267 ; U1.3@65.662,74.44 65.662,75.267 ; v1@69.191,126.872 69.494,125.171 ; v1@69.394,87.349 69.698,85.649 v1@70.001,87.349 ; v1(69.698,87.376) 69.698,79.303 65.662,75.267 ; v1@69.798,126.872 69.494,125.171 ; 烧入口1.3@62.524,91.291 v1(62.89,89.56) ; v1(62.89,89.56) 烧入口1.3@63.043,91.305 ; v1(62.89,89.56) 烧入口1.3@63.043,91.305 ; v1(62.89,89.56) 烧入口1.3@63.536,91.211 ; v1@63.043,89.713 烧入口1.3@63.043,91.44 v1@63.043,89.713 ; 烧入口1.3@63.043,91.305 62.59,89.613 烧入口1.3@63.043,91.305 ; 烧入口1.3@63.043,91.305 63.195,89.56 烧入口1.3@63.043,91.305
  BottomLayer w0.406: Mini_S2.1@48.909,123.154 51.554,123.154 55.298,126.898 v1(69.494,126.898) ; Mini_S2.1@48.92,122.926 51.373,123.154 ; Mini_S2.1@48.92,123.382 51.373,123.154 ; Mini_S2.1@48.991,122.524 51.373,123.154 ; Mini_S2.1@48.991,123.784 51.373,123.154 ; Mini_S2.1@49.129,122.136 51.373,123.154 ; Mini_S2.1@49.129,124.172 51.373,123.154 ; v1(62.89,89.56) 64.262,89.56 ; v1@62.924,89.257 64.262,89.56 ; v1@62.924,89.863 64.262,89.56 ; v1@69.468,126.595 67.767,126.898 ; v1@69.468,127.202 67.767,126.898 ; v1@69.521,126.595 71.222,126.898 v1@69.521,127.202 ; v1@69.671,87.072 67.97,87.376 ; v1@69.671,87.68 67.97,87.376 ; v1@69.724,87.072 71.425,87.376 v1@69.724,87.68 ; 64.262,89.56 66.446,87.376 v1(69.698,87.376) ; 67.767,126.898 v1(69.494,126.898) ; 67.97,87.376 v1(69.698,87.376) ; v1(69.494,126.898) 71.272,126.898 73.152,125.019 73.152,88.29 72.238,87.376 v1(69.698,87.376)
KEY3: Mini_S3.1 R38.6 U1.2 | length 194.7
  TopLayer w0.406: v1(62.05,138.35) 63.175,138.35 ; v1@62.091,138.048 63.175,138.35 ; v1@62.091,138.652 63.175,138.35 ; R38.6@65.259,105.334 69.164,105.334 ; R38.6@65.309,105.334 66.728,105.334 ; U1.2@66.475,73.373 66.475,74.966 ; U1.2@66.475,74.44 66.475,74.966 ; v1@69.709,106.305 69.164,105.334 ; v1(69.952,103.175) 71.984,103.175 ; v1@69.978,102.871 71.679,103.175 v1@69.978,103.478 ; v1@70.136,105.878 69.164,105.334 ; 63.175,138.35 64.075,137.45 64.075,132.45 64.5,132.025 70.525,132.025 72.034,130.516 72.034,103.226 71.984,103.175 ; 66.475,74.966 67.678,76.17 70.298,76.17 73.525,79.397 73.525,102.1 72.45,103.175 71.984,103.175 ; 69.164,105.334 v1(69.952,106.121) 69.164,105.334
  TopLayer w0.762: Mini_S3.1@21.132,123.31 21.989,126.735 ; Mini_S3.1@21.132,135.19 21.989,131.765 ; Mini_S3.1@21.989,123.154 Mini_S3.1@21.989,135.346 ; Mini_S3.1@21.989,123.205 21.989,126.735 ; Mini_S3.1@21.989,135.295 21.989,131.765 ; Mini_S3.1@22.846,123.31 21.989,126.735 ; Mini_S3.1@22.846,135.19 21.989,131.765
  BottomLayer w0.406: v1@69.648,103.202 69.952,104.902 v1@70.255,103.202 ; v1@69.648,106.094 69.952,104.394 ; v1(69.952,103.175) v1(69.952,106.121) 69.952,104.394 ; v1@70.255,106.094 69.952,104.394
  BottomLayer w0.762: Mini_S3.1@21.139,135.55 21.989,137.839 ; Mini_S3.1@21.989,135.346 21.989,137.839 ; Mini_S3.1@21.989,135.397 21.989,137.839 ; Mini_S3.1@22.839,135.55 21.989,137.839 ; 59.233,138.506 v1(62.05,138.35) ; v1@62.05,138.506 22.657,138.506 21.989,137.839
KEY4: Mini_S4.1 R38.5 U1.1 | length 219.5
  TopLayer w0.406: v1@62.847,139.381 62.025,140 ; v1@62.909,139.943 63.675,140 ; v1@63.052,139.948 62.025,140 ; v1@63.182,139.411 63.675,140 ; R38.5@65.259,104.534 70.142,104.534 71.12,105.512 71.12,129.875 v1(70.942,130.053) 71.12,128.283 ; R38.5@65.309,104.534 66.728,104.534 ; U1.1@67.262,73.373 68.948,73.373 74.312,78.737 74.312,103.013 72.822,104.503 72.822,132.997 65.528,132.997 64.862,133.663 64.862,138.813 63.675,140 ; v1@70.643,129.997 71.12,128.283 ; v1@71.247,130.057 71.12,128.283 ; v1@72.67,132.75 72.822,131.008 ; v1@72.908,132.453 71.18,132.997 ; v1@72.991,133.054 71.18,132.997 ; v1@73.075,132.75 v1(72.975,132.75) ; v1@73.275,132.697 72.822,131.008 ; 62.025,140 63.675,140 ; 62.025,140 v1(62.992,139.649) 63.675,140 ; 71.18,132.997 v1(72.975,132.75) ; 72.822,131.008 v1(72.975,132.75)
  TopLayer w0.762: Mini_S4.1@8.839,123.154 Mini_S4.1@8.839,135.346
  BottomLayer w0.406: v1(70.942,130.053) 72.328,130.053 ; v1@70.976,129.75 72.328,130.053 ; v1@70.976,130.356 72.328,130.053 ; v1@72.671,132.723 72.975,131.023 ; v1@73.279,132.723 72.975,131.023 ; 72.328,130.053 72.975,130.7 v1(72.975,132.75) 72.975,131.023
  BottomLayer w0.762: Mini_S4.1@8.839,135.346 8.839,138.125 10.363,139.649 v1(62.992,139.649) 60.198,139.649
LAMP1: R1.2 U2.16 | length 13
  TopLayer w0.762: R1.2@18.849,106.786 18.849,104.875 ; R1.2@18.857,106.664 18.849,104.875 ; 21.762,102.225 U2.16@24.429,102.225 21.499,102.225 18.849,104.875
LAMP2: R2.2 U2.15 | length 11
  TopLayer w0.762: R2.2@21.599,106.659 21.599,104.7 ; R2.2@21.599,106.786 21.599,104.7 ; U2.15@25.699,102.225 25.699,103.425 ; 21.599,104.7 22.149,104.15 24.974,104.15 25.699,103.425 ; 25.699,103.425 25.699,102.86 25.699,103.425
LAMP3: R4.2 U2.14 | length 6.6
  TopLayer w0.762: R4.2@24.324,106.786 24.324,106.416 26.969,103.771 ; U2.14@26.969,102.225 26.969,103.771 ; U2.14@26.969,102.86 26.969,103.771
LAMP4: R5.2 U2.13 | length 7.7
  TopLayer w0.762: R5.2@27.074,106.659 27.074,105.283 ; R5.2@27.074,106.786 27.074,105.283 ; U2.13@28.239,102.225 28.239,104.118 ; U2.13@28.239,102.86 28.239,104.118 ; 27.074,105.283 28.239,104.118
LAMP5: R6.2 U2.12 | length 8.2
  TopLayer w0.762: U2.12@29.509,102.225 29.509,104.325 ; U2.12@29.509,102.86 29.509,104.325 ; R6.2@29.824,106.659 29.824,104.64 ; R6.2@29.824,106.786 29.824,104.64 ; 29.509,104.325 29.824,104.64
LAMP6: R8.2 U2.11 | length 9.5
  TopLayer w0.762: U2.11@30.779,102.225 30.779,103.268 ; R8.2@32.549,106.659 30.967,105.204 ; R8.2@32.549,106.786 30.967,105.204 ; U2.11@30.779,102.86 30.967,103.456 ; U2.11@30.779,102.86 30.779,103.268 ; U2.11@30.779,102.86 30.779,103.268 ; U2.11@30.779,102.86 30.967,103.456 ; 30.779,103.268 30.967,103.456 ; 30.967,103.456 30.967,105.204
LAMP7: R10.2 U2.10 | length 10.5
  TopLayer w0.762: U2.10@32.049,102.225 32.11,102.286 32.11,104.236 32.749,104.875 34.349,104.875 ; R10.2@35.307,106.769 35.307,105.833 ; 34.349,104.875 35.307,105.833 ; 34.349,104.875 R10.2@35.307,106.642 ; 35.307,105.833 R10.2@35.307,106.642 ; 35.307,105.833 R10.2@35.307,106.642
LAMP8: R11.2 U4.16 | length 14.7
  TopLayer w0.762: R11.2@18.83,39.008 22.657,39.008 23.449,39.8 U4.16@23.449,43.98 23.449,41.313 ; R11.2@18.957,39.008 21.878,39.008
LAMP9: R13.2 U4.15 | length 10.6
  TopLayer w0.762: R13.2@18.813,41.725 21.024,41.725 ; R13.2@18.94,41.725 21.024,41.725 ; U4.15@23.449,45.25 22.291,45.25 ; 21.024,41.725 21.374,42.075 21.374,44.334 22.291,45.25 ; 22.291,45.25 22.814,45.25 22.291,45.25
LAMP10: R14.2 U4.14 | length 10
  TopLayer w0.762: R14.2@18.813,44.5 18.964,44.35 19.524,44.35 21.694,46.52 ; R14.2@18.94,44.5 21.626,46.452 ; U4.14@22.814,46.52 21.694,46.52 ; U4.14@23.449,46.52 21.694,46.52
LAMP11: R15.2 U4.13 | length 11.4
  TopLayer w0.762: R15.2@18.813,47.3 19.303,47.79 U4.13@23.449,47.79 ; R15.2@18.94,47.3 22.081,47.79 22.814,47.79 20.147,47.79
LAMP12: R16.2 U4.12 | length 9.1
  TopLayer w0.762: R16.2@18.813,50.1 19.854,49.06 ; R16.2@18.94,50.1 19.854,49.06 ; 20.147,49.06 U4.12@22.814,49.06 ; U4.12@23.449,49.06 19.854,49.06
LAMP13: R17.2 U4.11 | length 10.2
  TopLayer w0.762: R17.2@18.813,52.875 21.359,50.33 ; R17.2@18.94,52.875 21.065,50.624 ; U4.11@22.814,50.33 21.359,50.33 ; U4.11@23.449,50.33 21.359,50.33
LAMP14: R19.2 U4.10 | length 9.9
  TopLayer w0.762: R19.2@18.813,55.675 20.074,55.675 ; R19.2@18.94,55.675 20.074,55.675 ; U4.10@22.814,51.6 21.774,51.6 ; U4.10@23.449,51.6 21.774,51.6 ; 20.074,55.675 21.224,54.525 21.224,52.15 21.774,51.6
LAMP15: R20.2 U7.16 | length 12.9
  TopLayer w0.762: R20.2@21.963,12.05 24.574,12.05 ; R20.2@22.09,12.05 24.574,12.05 ; 25.949,13.963 U7.16@25.949,16.63 25.949,13.425 24.574,12.05
LAMP16: R21.2 U7.15 | length 7.8
  TopLayer w0.762: R21.2@21.963,14.775 23.599,14.775 ; R21.2@22.09,14.775 23.599,14.775 ; U7.15@25.949,17.9 24.968,17.9 24.074,17.006 24.074,15.25 23.599,14.775
LAMP17: R22.2 U7.14 | length 11.5
  TopLayer w0.762: R22.2@21.963,17.525 22.976,17.525 ; U7.14@25.949,19.17 24.621,19.17 ; R22.2@22.09,17.525 22.976,17.525 ; R22.2@22.09,17.525 24.621,19.17 ; R22.2@22.09,17.525 22.976,17.525 ; 22.976,17.525 24.621,19.17 ; 24.621,19.17 U7.14@25.314,19.17 ; 24.621,19.17 U7.14@25.314,19.17 ; 24.621,19.17 U7.14@25.314,19.17
LAMP18: R25.2 U7.13 | length 12.4
  TopLayer w0.762: R25.2@21.963,20.25 22.153,20.44 U7.13@25.949,20.44 ; R25.2@22.09,20.25 U7.13@25.032,20.44 ; R25.2@22.64,20.286 25.314,20.44 R25.2@22.647,20.44
LAMP19: R27.2 U7.12 | length 8.3
  TopLayer w0.762: R27.2@21.963,23 23.254,21.71 ; R27.2@22.09,23 23.254,21.71 ; U7.12@25.314,21.71 23.254,21.71 ; U7.12@25.949,21.71 23.254,21.71
LAMP20: R29.2 U7.11 | length 6.2
  TopLayer w0.762: R29.2@21.963,25.75 21.963,25.475 24.458,22.98 ; U7.11@25.314,22.98 24.458,22.98 ; U7.11@25.949,22.98 24.458,22.98
LAMP21: R37.1 U7.10 | length 11.7
  TopLayer w0.762: R37.1@21.963,28.485 23.09,28.485 ; U7.10@25.949,24.25 24.805,24.25 ; R37.1@22.09,28.485 23.09,28.485 ; R37.1@22.09,28.485 23.524,28.05 ; R37.1@22.09,28.485 23.09,28.485 ; 23.09,28.485 23.524,28.05 ; 23.524,28.05 23.524,25.53 24.805,24.25 ; 24.805,24.25 25.314,24.25 24.805,24.25
LED1: 
LED2: 
LED3: 
LED4: 
LED5: 
LED6: 
LED7: 
LED8: 
LEDK1: LED6.K R1.1 | length 85.9
  TopLayer w0.762: LED6.K@9.799,107.93 11.164,107.93 ; LED6.K@9.872,107.491 11.164,107.93 ; LED6.K@9.872,108.369 11.164,107.93 ; R1.1@18.849,109.072 18.087,108.31 ; 11.164,107.93 11.543,108.31 18.087,108.31 ; 18.087,108.31 18.857,108.95 18.087,108.31
  BottomLayer w0.762: LED6.K@2.286,115.049 1.212,113.974 ; LED6.K@2.526,115.281 1.212,113.974 ; LED6.K@2.601,114.93 LED6.K@2.799,114.93 ; LED6.K@2.633,107.518 1.212,108.329 ; LED6.K@2.831,107.487 5.911,107.93 LED6.K@2.831,108.373 ; LED6.K@2.831,114.487 5.911,114.93 LED6.K@2.831,115.373 ; LED6.K@2.848,108.372 1.212,108.329 ; LED6.K@2.981,114.524 1.212,113.974 ; LED6.K@9.601,114.93 LED6.K@2.799,114.93 ; LED6.K@9.767,107.487 6.688,107.93 ; LED6.K@9.767,108.373 6.688,107.93 ; LED6.K@9.767,114.487 6.688,114.93 ; LED6.K@9.767,115.373 6.688,114.93 ; LED6.K@9.799,114.93 6.688,114.93 ; 1.212,108.329 1.212,113.974 ; 1.212,108.329 1.611,107.93 ; 1.212,108.329 LED6.K@2.799,107.93 ; 1.212,113.974 LED6.K@2.799,114.93 ; 1.611,107.93 LED6.K@2.799,107.93 ; 1.611,107.93 2.716,107.493 1.611,107.93 ; 1.611,107.93 2.716,108.367 1.611,107.93 ; 1.611,107.93 LED6.K@2.799,107.93 ; 1.611,107.93 LED6.K@2.799,107.93 ; LED6.K@2.799,107.93 LED6.K@9.799,107.93 6.688,107.93
LEDK2: LED4.K R2.1 | length 118.6
  TopLayer w0.762: LED4.K@9.358,142.498 9.799,140.651 ; LED4.K@10.241,142.498 9.799,140.651 ; R2.1@21.599,109.072 21.599,120.126 18.085,123.64 18.085,132.365 9.799,140.651 ; R2.1@21.599,109.199 21.599,112.12 ; 9.799,140.651 LED4.K@9.799,142.55 9.799,140.651
  BottomLayer w0.762: LED4.K@2.286,149.669 1.212,148.594 ; LED4.K@2.526,149.901 1.212,148.594 ; LED4.K@2.601,149.55 LED4.K@2.799,149.55 ; LED4.K@2.633,142.138 1.212,142.949 ; LED4.K@2.831,142.107 5.911,142.55 LED4.K@2.831,142.993 ; LED4.K@2.831,149.107 5.911,149.55 LED4.K@2.831,149.993 ; LED4.K@2.848,142.992 1.212,142.949 ; LED4.K@2.981,149.144 1.212,148.594 ; LED4.K@9.601,149.55 LED4.K@2.799,149.55 ; LED4.K@9.767,142.107 6.688,142.55 ; LED4.K@9.767,142.993 6.688,142.55 ; LED4.K@9.767,149.107 6.688,149.55 ; LED4.K@9.767,149.993 6.688,149.55 ; LED4.K@9.799,149.55 6.688,149.55 ; 1.212,142.949 1.611,142.55 ; 1.212,142.949 1.212,148.594 ; 1.212,142.949 LED4.K@2.799,142.55 ; 1.212,148.594 LED4.K@2.799,149.55 ; 1.611,142.55 LED4.K@2.799,142.55 ; 1.611,142.55 2.716,142.113 1.611,142.55 ; 1.611,142.55 2.716,142.987 1.611,142.55 ; 1.611,142.55 LED4.K@2.799,142.55 ; 1.611,142.55 LED4.K@2.799,142.55 ; LED4.K@2.799,142.55 LED4.K@9.799,142.55 6.688,142.55
LEDK3: LED3.K R4.1 | length 115.2
  TopLayer w0.762: LED3.K@21.029,142.55 23.261,142.55 ; LED3.K@21.073,142.108 23.261,142.55 ; LED3.K@21.073,142.992 23.261,142.55 ; R4.1@24.324,109.072 24.324,141.487 23.261,142.55 ; R4.1@24.324,109.199 24.324,112.12
  BottomLayer w0.762: LED3.K@20.516,149.669 19.442,148.594 ; LED3.K@20.756,149.901 19.442,148.594 ; LED3.K@20.831,149.55 LED3.K@21.029,149.55 ; LED3.K@20.863,142.138 19.442,142.949 ; LED3.K@21.061,142.107 24.141,142.55 LED3.K@21.061,142.993 ; LED3.K@21.061,149.107 24.141,149.55 LED3.K@21.061,149.993 ; LED3.K@21.078,142.992 19.442,142.949 ; LED3.K@21.211,149.144 19.442,148.594 ; LED3.K@27.831,149.55 LED3.K@21.029,149.55 ; LED3.K@27.997,142.107 24.918,142.55 ; LED3.K@27.997,142.993 24.918,142.55 ; LED3.K@27.997,149.107 24.918,149.55 ; LED3.K@27.997,149.993 24.918,149.55 ; LED3.K@28.029,149.55 24.918,149.55 ; 19.442,142.949 19.841,142.55 ; 19.442,142.949 19.442,148.594 ; 19.442,142.949 LED3.K@21.029,142.55 ; 19.442,148.594 LED3.K@21.029,149.55 ; 19.841,142.55 LED3.K@21.029,142.55 ; 19.841,142.55 20.946,142.113 19.841,142.55 ; 19.841,142.55 20.946,142.987 19.841,142.55 ; 19.841,142.55 LED3.K@21.029,142.55 ; 19.841,142.55 LED3.K@21.029,142.55 ; LED3.K@21.029,142.55 LED3.K@28.029,142.55 24.918,142.55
